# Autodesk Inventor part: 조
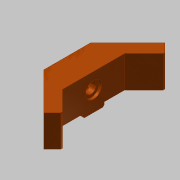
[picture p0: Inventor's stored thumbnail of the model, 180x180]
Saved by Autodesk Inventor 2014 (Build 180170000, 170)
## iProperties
Created: 2019-04
Part Number: 조
Material: 알루미늄 6061
Document SubType Name: Modeling
Designer: mduedu
Density: 1 g/cm^3
Appearance: 매끄러움 - 연한 주황색
Author: mduedu
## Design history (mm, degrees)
sketch "스케치1"
  geometry: L1 (45.962, 0)-(0, -45.962); L2 (0, -45.962)-(-45.962, 0); L3 (-45.962, 0)-(0, 45.962); L4 (0, 45.962)-(45.962, 0); L5 (45.962, 0)-(-45.962, 0); L6 (0, -45.962)-(0, 45.962); 1 further point
  constraints: 12 end point, 2 midpoint, 2 parallel, 2 perpendicular, 1 horizontal
  dimensions: "d0" = 65 distance of L1.end L2.end
extrude "돌출1" new body sketch "스케치1" distance "d2" = 27; taper "d3" = 0 deg
chamfer "모따기1" distance "d4" = 25; stored, may be unused: second distance "d5" = 2, angle "d6" = 45 deg
sketch "스케치2"
  geometry: L1 (-17.678, 28.284)-(-45.962, 0) reference; L2 (-17.678, 28.284)-(17.678, 28.284) reference; L3 (45.962, 0)-(17.678, 28.284) reference; L4 (-45.962, 0)-(0, -45.962) reference; L5 (0, -45.962)-(45.962, 0) reference; L6 (-23.536, 8.284)-(23.536, 8.284); L7 (-23.536, 8.284)-(-38.891, -7.071); L8 (38.891, -7.071)-(23.536, 8.284); 1 further point
  constraints: 6 end point, 3 parallel, 2 point on line
  dimensions: "d7" = 20 distance between parallel lines of L6 L2; "d8" = 10 distance between parallel lines of L1 L7; "d9" = 10 distance between parallel lines of L3 L8
extrude "돌출2" cut sketch "스케치2" stored distance "d10" = 27; taper "d11" = 0 deg
sketch "스케치3"
  geometry: L1 (63.64, -27)-(63.64, 0) reference; L2 (56.569, -27)-(63.64, -27) reference; L3 (-28.284, -27)-(-28.284, 0) reference; L4 (-28.284, -27)-(-21.213, -27) reference; L5 (63.64, -27)-(25.678, -27); L6 (25.678, -27)-(25.678, -24); L7 (25.678, -24)-(63.64, -24); L8 (63.64, -24)-(63.64, -27); L9 (-28.284, -27)-(9.678, -27); L10 (9.678, -27)-(9.678, -24); L11 (9.678, -24)-(-28.284, -24); L12 (-28.284, -24)-(-28.284, -27); L13 (41.213, 0)-(-5.858, 0) reference; L14 (17.678, -27)-(17.678, 0)
  constraints: 18 end point, 4 parallel, 2 horizontal, 2 perpendicular, 1 midpoint, 1 symmetric about line
  dimensions: "d12" = 3 distance between parallel lines of L5 L7; "d14" = 16 distance between parallel lines of L10 L6
extrude "돌출3" cut sketch "스케치3" stored distance "d15" = 27; taper "d16" = 0 deg
sketch "스케치4"
  geometry: L1 (31.536, -27)-(15.536, -27) reference; L2 (31.536, -24)-(47.071, -24) reference; 3 further points
  constraints: 1 midpoint, 1 vertical alignment
  dimensions: "d17" = 12 distance from line of L2 point (23.536, -12)
hole "구멍1" sketch "스케치4" at (23.536, -12) diameter "d18" = 8; stored, may be unused: countersink angle "d22" = 90 deg, drill point angle "d24" = 118 deg; dims "d19" = 6, "d20" = 12.5, "d21" = 2, "d23" = 14
node "작업 평면1"
sketch "스케치5"
  geometry: L1 (0, -15)-(0, 0); L2 (-50, -4)-(50, -4); L3 (50, -4)-(50, -1.75); L4 (-50, -1.75)-(-50, -4); L5 (12, -1.75)-(12, -2.75); L6 (12, -2.75)-(-12, -2.75); L7 (-12, -2.75)-(-12, -1.75); L8 (50, -1.75)-(12, -1.75); L9 (-12, -1.75)-(-50, -1.75); C1 r 4 at (0, 0) reference; 2 further points
  constraints: 18 end point, 4 parallel, 2 midpoint, 2 vertical, 2 vertical alignment, 1 collinear, 1 horizontal, 1 perpendicular, 1 tangent
  dimensions: "d26" = 2.5 diameter of L6 L2; "d28" = 4.5 diameter of L8 L2; "d29" = 24 distance of L5.end L6.end; "d30" = 100 distance between parallel lines of L3 L4
revolve "회전1" sketch "스케치5" stored, may be unused: angle "d31" = 90 deg
chamfer "모따기2" distance "d32" = 1; stored, may be unused: second distance "d33" = 2, angle "d34" = 45 deg
chamfer "모따기3" distance "d35" = 1; stored, may be unused: second distance "d36" = 2, angle "d37" = 45 deg
node "솔리드1"
other parameters: "d25" = -5
